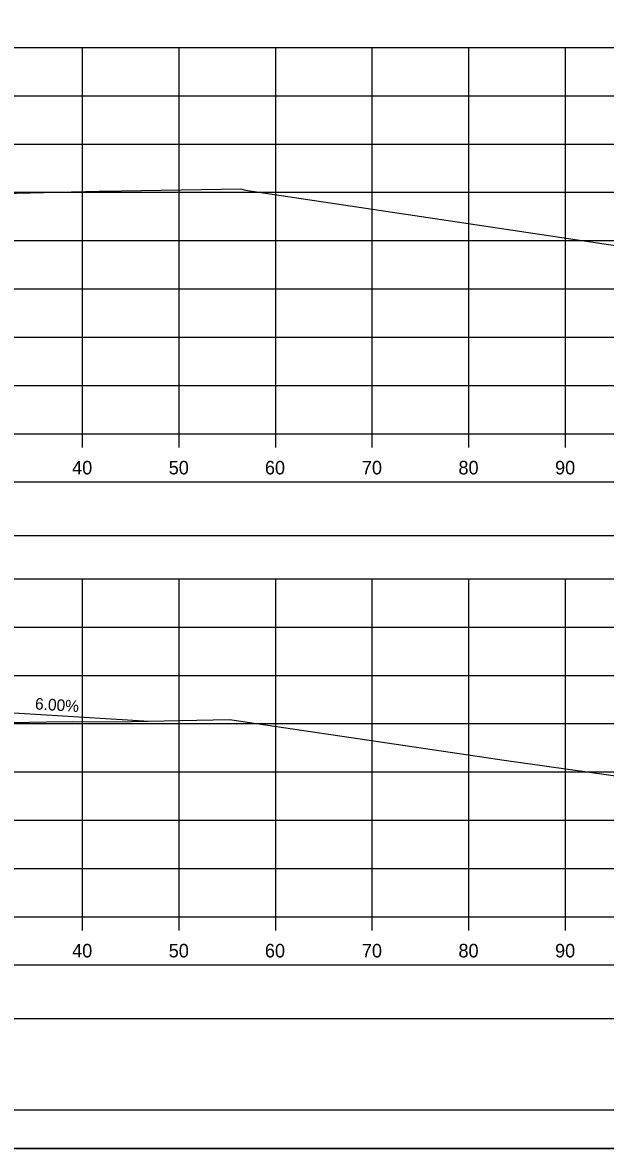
# Model space of a CAD drawing. Extents: x 1202951 to 1376887, y 378065 to 728038.
# Drawn here: x 1376618.5 to 1376678.8, y 378621.2 to 378737.7 of the extents above; entities that cross this region are included whole.
import ezdxf

# ---------------------------------------------------------------- set-up
doc = ezdxf.new("R2010")
doc.units = 0
for name, color, linetype in [('R_Alt Surface', 7, 'Continuous'), ('R_Axis', 7, 'Continuous'), ('R_Axis Annot', 7, 'Continuous'), ('R_Border', 7, 'Continuous'), ('R_Drive', 7, 'Continuous'), ('R_Exist Surface', 7, 'Continuous'), ('R_Grid', 7, 'Continuous'), ('R_No Plot', 7, 'Continuous'), ('R_Xsect Elev', 7, 'Continuous')]:
    doc.layers.add(name, color=color, linetype=linetype)

msp = doc.modelspace()

# ---------------------------------------------------------------- linework, layer by layer
at = {"layer": 'R_Alt Surface'}
for points in [[(1376615.43, 378684.63), (1376726.14, 378684.63), (1376726.14, 378690.15), (1376615.43, 378690.15)], [(1376615.43, 378634.63), (1376726.14, 378634.63), (1376726.14, 378640.15), (1376615.43, 378640.15)]]:
    msp.add_lwpolyline(points, close=True, dxfattribs=at)
at = {"layer": 'R_Axis'}
for p, q in [((1376434.67, 378695.15), (1376734.67, 378695.15)), ((1376624.67, 378693.75), (1376624.67, 378695.15)), ((1376634.67, 378693.75), (1376634.67, 378695.15)), ((1376644.67, 378693.75), (1376644.67, 378695.15)), ((1376654.67, 378693.75), (1376654.67, 378695.15)), ((1376664.67, 378693.75), (1376664.67, 378695.15)), ((1376674.67, 378693.75), (1376674.67, 378695.15)), ((1376434.67, 378645.15), (1376734.67, 378645.15)), ((1376624.67, 378643.75), (1376624.67, 378645.15)), ((1376634.67, 378643.75), (1376634.67, 378645.15)), ((1376644.67, 378643.75), (1376644.67, 378645.15)), ((1376654.67, 378643.75), (1376654.67, 378645.15)), ((1376664.67, 378643.75), (1376664.67, 378645.15)), ((1376674.67, 378643.75), (1376674.67, 378645.15))]:
    msp.add_line(p, q, dxfattribs=at)
at = {"layer": 'R_Border'}
msp.add_line((1376742.85, 378625.15), (1376426.67, 378625.15), dxfattribs=at)
at = {"layer": 'R_Drive'}
msp.add_line((1376612.67, 378666.55), (1376631.56, 378665.41), dxfattribs=at)
at = {"layer": 'R_Exist Surface'}
for points in [[(1376613.51, 378719.96), (1376626.38, 378720.26), (1376626.49, 378720.26), (1376628.69, 378720.3), (1376641.04, 378720.5), (1376641.54, 378720.39), (1376693.2, 378712.63)], [(1376611.95, 378665.16), (1376620.93, 378665.32), (1376623.59, 378665.38), (1376628.05, 378665.34), (1376639.9, 378665.58), (1376668.56, 378661.35), (1376689.67, 378658.38)]]:
    msp.add_lwpolyline(points, dxfattribs=at)
at = {"layer": 'R_Grid'}
for p, q in [((1376434.67, 378735.15), (1376734.67, 378735.15)), ((1376624.67, 378695.15), (1376624.67, 378735.15)), ((1376634.67, 378695.15), (1376634.67, 378735.15)), ((1376644.67, 378695.15), (1376644.67, 378735.15)), ((1376654.67, 378695.15), (1376654.67, 378735.15)), ((1376664.67, 378695.15), (1376664.67, 378735.15)), ((1376674.67, 378695.15), (1376674.67, 378735.15)), ((1376434.67, 378730.15), (1376734.67, 378730.15)), ((1376434.67, 378725.15), (1376734.67, 378725.15)), ((1376434.67, 378720.15), (1376734.67, 378720.15)), ((1376434.67, 378715.15), (1376734.67, 378715.15)), ((1376434.67, 378710.15), (1376734.67, 378710.15)), ((1376434.67, 378705.15), (1376734.67, 378705.15)), ((1376434.67, 378700.15), (1376734.67, 378700.15)), ((1376434.67, 378695.15), (1376734.67, 378695.15)), ((1376434.67, 378680.15), (1376734.67, 378680.15)), ((1376624.67, 378645.15), (1376624.67, 378680.15)), ((1376634.67, 378645.15), (1376634.67, 378680.15)), ((1376644.67, 378645.15), (1376644.67, 378680.15)), ((1376654.67, 378645.15), (1376654.67, 378680.15)), ((1376664.67, 378645.15), (1376664.67, 378680.15)), ((1376674.67, 378645.15), (1376674.67, 378680.15)), ((1376434.67, 378675.15), (1376734.67, 378675.15)), ((1376434.67, 378670.15), (1376734.67, 378670.15)), ((1376434.67, 378665.15), (1376734.67, 378665.15)), ((1376434.67, 378660.15), (1376734.67, 378660.15)), ((1376434.67, 378655.15), (1376734.67, 378655.15)), ((1376434.67, 378650.15), (1376734.67, 378650.15)), ((1376434.67, 378645.15), (1376734.67, 378645.15))]:
    msp.add_line(p, q, dxfattribs=at)
at = {"layer": 'R_No Plot'}
msp.add_line((1376414.27, 378621.18), (1376747.6, 378621.18), dxfattribs=at)
for points in [[(1376414.26, 378834.51), (1376747.6, 378834.51), (1376747.6, 378621.17), (1376414.26, 378621.17)], [(1376660.59, 378830.61), (1376680.21, 378830.61), (1376680.21, 378820.73), (1376696.32, 378820.73), (1376719.52, 378820.73), (1376719.64, 378792.58), (1376742.85, 378792.58), (1376742.85, 378625.15), (1376426.67, 378625.15), (1376426.67, 378830.61)]]:
    msp.add_lwpolyline(points, close=True, dxfattribs=at)

# ---------------------------------------------------------------- texts
at = {"layer": 'R_Axis Annot'}
for s, p in [('40', (1376623.59, 378690.95)), ('50', (1376633.59, 378690.95)), ('60', (1376643.55, 378690.95)), ('70', (1376653.59, 378690.95)), ('80', (1376663.59, 378690.95)), ('90', (1376673.59, 378690.95)), ('40', (1376623.59, 378640.95)), ('50', (1376633.59, 378640.95)), ('60', (1376643.55, 378640.95)), ('70', (1376653.59, 378640.95)), ('80', (1376663.59, 378640.95)), ('90', (1376673.59, 378640.95))]:
    msp.add_text(s, height=1.4, dxfattribs=at).set_placement(p)
at = {"layer": 'R_Xsect Elev'}
msp.add_text('6.00%', height=1.2, rotation=356.5664, dxfattribs=at).set_placement((1376619.72, 378666.62))

doc.saveas('drawing.dxf')
